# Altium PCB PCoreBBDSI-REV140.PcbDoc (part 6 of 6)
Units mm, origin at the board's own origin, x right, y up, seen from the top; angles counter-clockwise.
Board outline 100 x 72 mm, 6 copper layers (Top Layer, Int1 (GND), Int2 (Sign), Int3 (Sign), Int4 (GND), Bottom Layer), stack 1.551 mm thick; 358 components, 403 nets, 1535 pads, 844 vias.
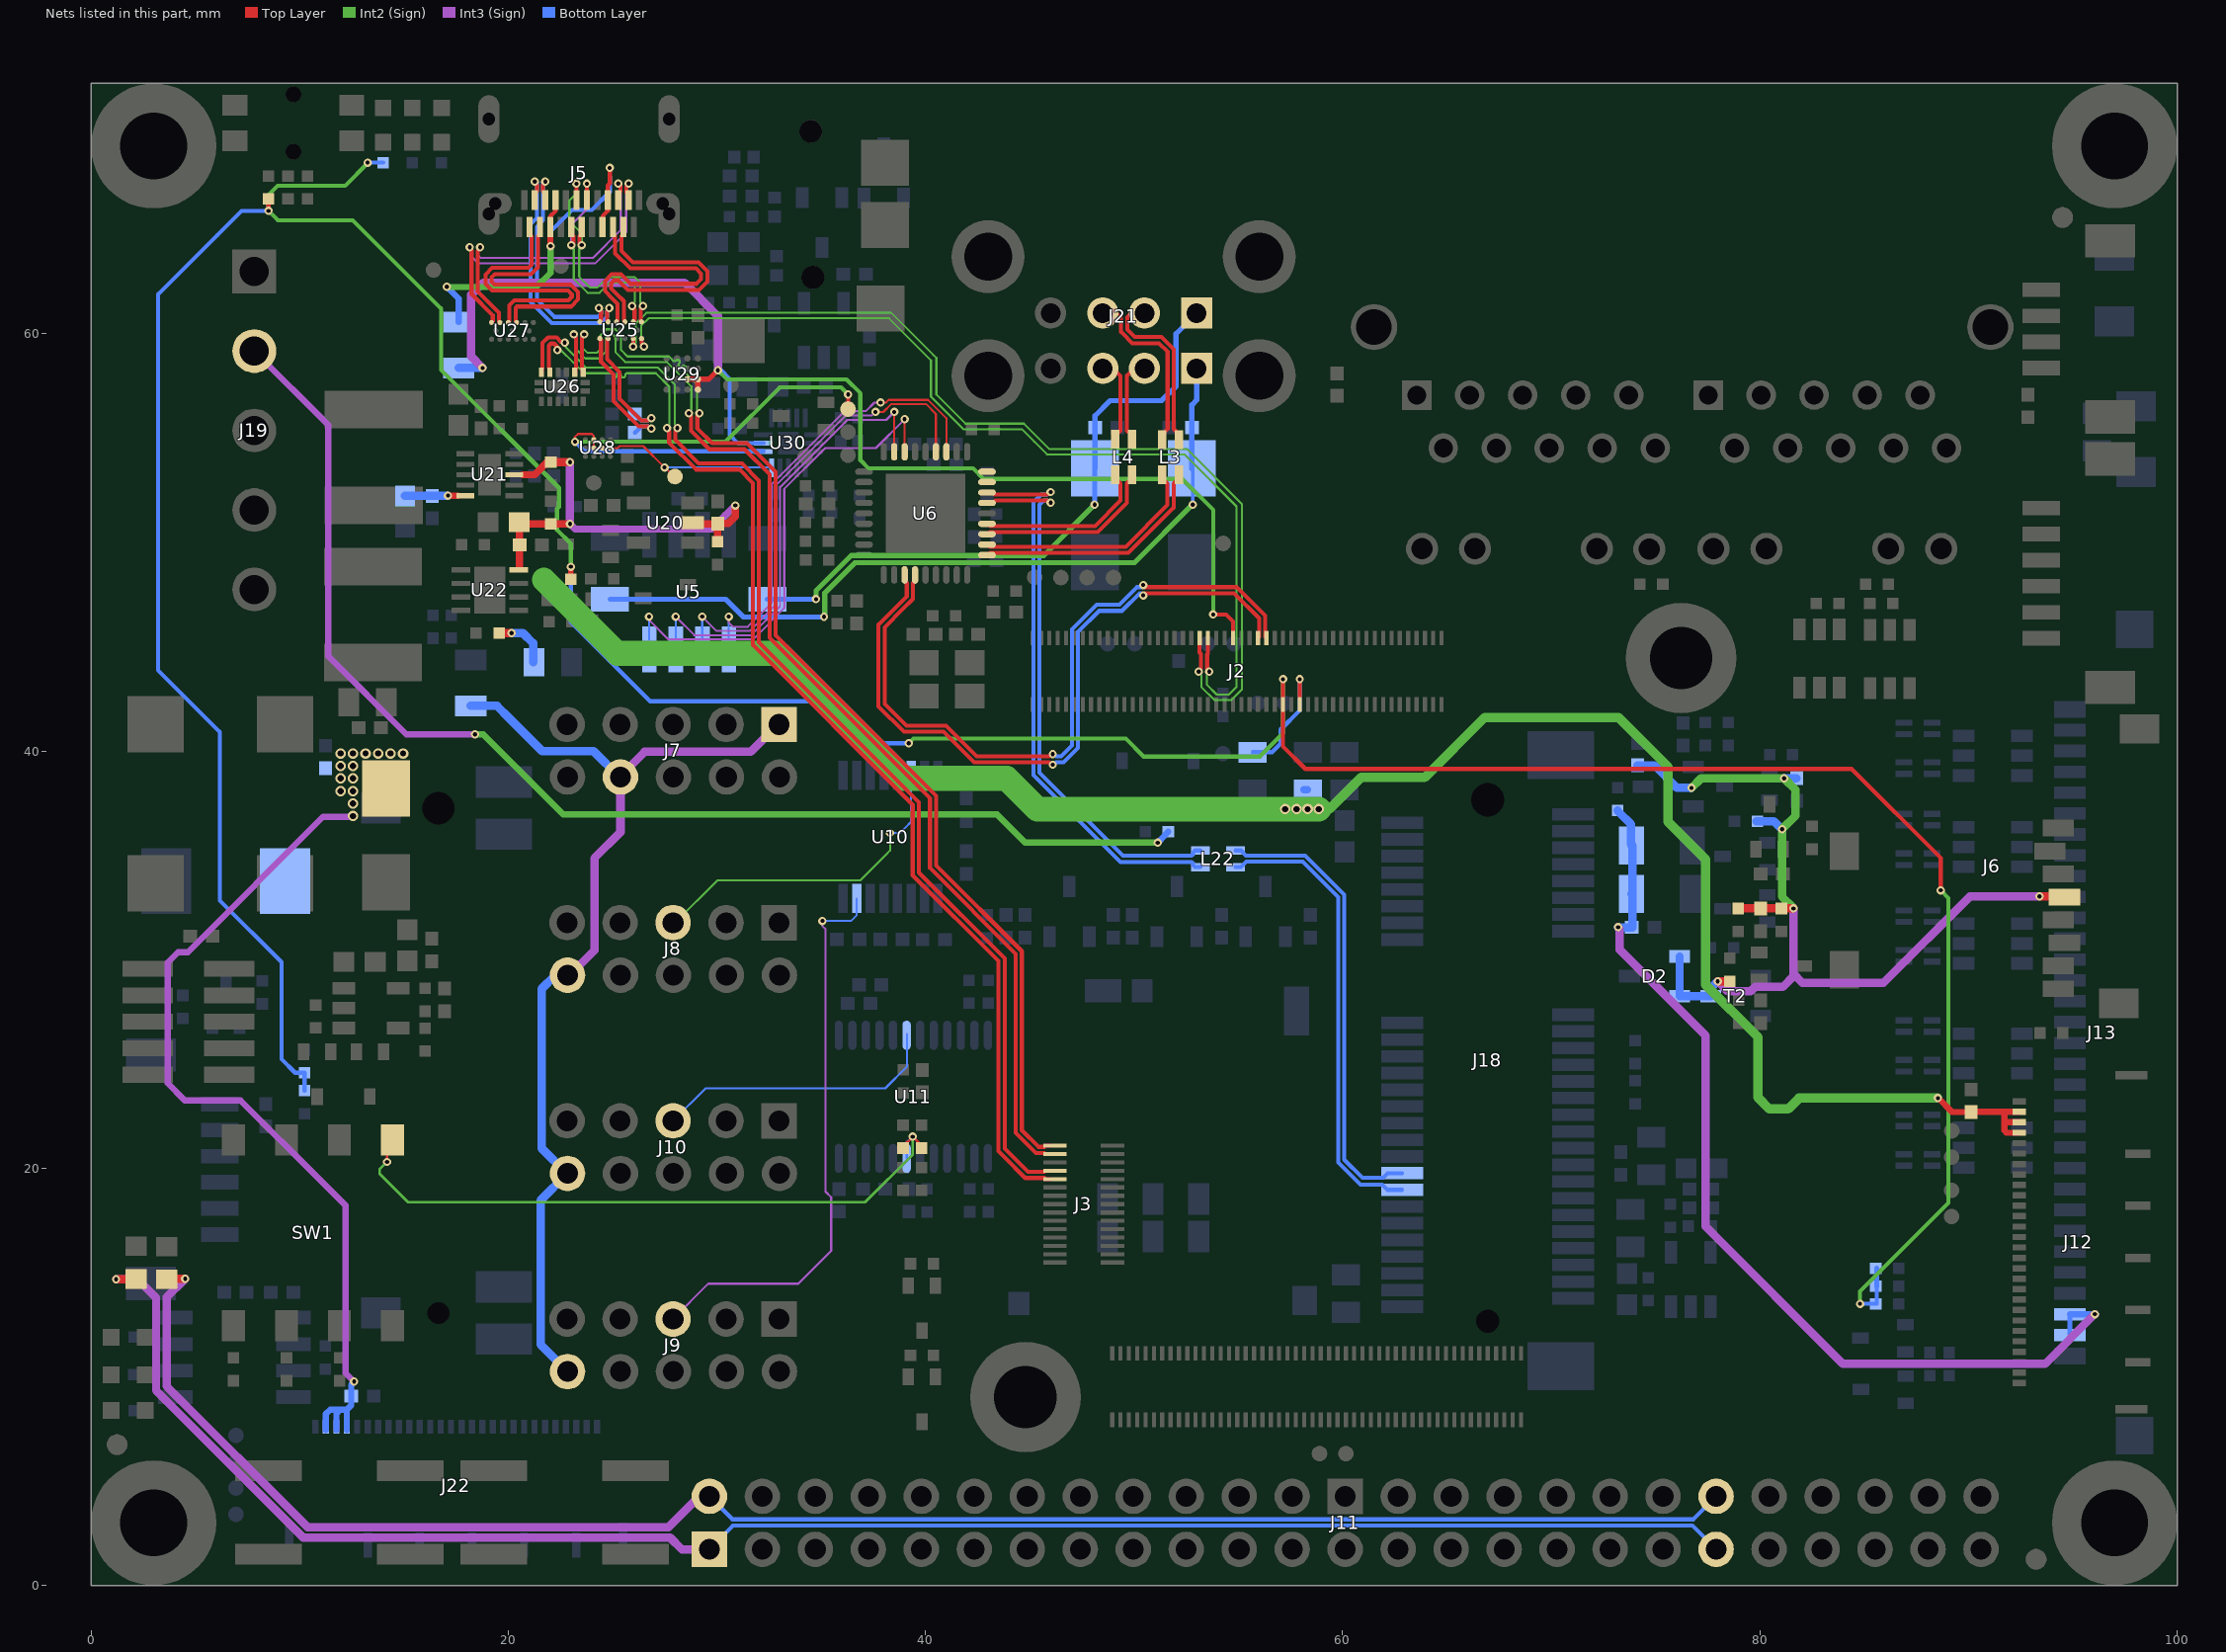
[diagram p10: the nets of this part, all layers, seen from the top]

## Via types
v1: diameter 0.4, hole 0.2, Top Layer to Bottom Layer, tented both sides, 716 vias
v2: diameter 0.5, hole 0.3, Top Layer to Bottom Layer, tented both sides, 102 vias
v3: diameter 0.4, hole 0.2, Top Layer to Bottom Layer, tented bottom, 16 vias
v4: diameter 0.9, hole 0.9, Top Layer to Bottom Layer, 6 vias
v5: diameter 0.5, hole 0.5, Top Layer to Bottom Layer, 2 vias
v6: diameter 3.2, hole 3.2, Top Layer to Bottom Layer, tented both sides, 2 vias

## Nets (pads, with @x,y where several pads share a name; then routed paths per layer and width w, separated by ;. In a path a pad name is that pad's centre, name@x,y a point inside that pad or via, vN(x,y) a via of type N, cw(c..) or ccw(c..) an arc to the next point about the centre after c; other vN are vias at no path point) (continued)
SS_TX2_N: C96.1 U25.C1 | length 6.6
  Top Layer w0.193: U25.C1@24.39,59.77 24.39,59.755 24.443,59.701 24.443,58.652 25.047,58.048 25.047,56.765 26.253,55.558 26.701,55.558 26.804,55.455 v1(26.86,55.455)
  Bottom Layer w0.193: C96.1@26.06,55.265 26.08,55.265 26.293,55.478 26.293,55.496 26.356,55.558 26.701,55.558 26.804,55.455 v1(26.86,55.455)
SS_TX2_P: C95.1 U25.C2 | length 6.1
  Top Layer w0.193: U25.C2@24.79,59.77 24.79,59.755 24.737,59.701 24.737,58.773 25.34,58.17 25.34,56.886 26.375,55.851 26.701,55.851 26.804,55.955 v1(26.86,55.955)
  Bottom Layer w0.193: C95.1@26.06,56.145 26.08,56.145 26.293,55.931 26.293,55.914 26.356,55.851 26.701,55.851 26.804,55.955 v1(26.86,55.955)
SSRX1_N: J5.B10 U27.A2 | length 15.2
  Top Layer w0.193: v1(18.65,64.14) 18.65,64.084 18.533,63.967 18.533,63.622 18.533,62.027 19.549,61.011 19.549,60.606 19.602,60.552 U27.A2@19.602,60.537 ; J5.B10@25.27,66.415 25.27,66.74 J5.B10@25.323,66.793 ; v1(25.27,67.2) 25.27,67.19 25.373,67.087 25.373,66.803 25.363,66.793 J5.B10@25.323,66.793 ; J5.B10@25.37,66.84 J5.B10@25.323,66.793
  Int3 (Sign) w0.1: v1(18.65,64.14) 18.65,64.077 18.531,63.958 18.531,63.79 18.691,63.63 24.05,63.63 25.389,64.969 25.389,67.018 25.27,67.137 v1(25.27,67.2)
SSRX1_P: J5.B11 U27.A1 | length 16.1
  Top Layer w0.193: v1(18.15,64.14) 18.15,64.084 18.24,63.994 18.24,63.743 18.24,61.905 19.256,60.89 19.256,60.606 19.202,60.552 U27.A1@19.202,60.537 ; J5.B11@25.663,66.847 J5.B11@25.667,66.843 ; J5.B11@25.77,66.415 25.77,66.74 J5.B11@25.717,66.793 ; v1(25.77,67.2) 25.77,67.144 25.667,67.041 J5.B11@25.667,66.843 ; J5.B11@25.667,66.843 25.667,66.803 25.677,66.793 J5.B11@25.717,66.793 ; J5.B11@25.667,66.843 J5.B11@25.717,66.793
  Int3 (Sign) w0.1: v1(18.15,64.14) 18.15,64.077 18.269,63.958 18.269,63.682 18.582,63.368 24.158,63.368 25.651,64.861 25.651,67.018 25.77,67.137 v1(25.77,67.2)
SSRX2_N: J5.A10 U27.A4 | length 13.2
  Top Layer w0.193: U27.A4@20.402,60.537 20.402,60.552 20.349,60.606 20.349,61.239 20.411,61.301 23.001,61.301 23.34,61.64 23.34,62.01 22.985,62.365 19.34,62.365 19.203,62.502 19.203,62.712 19.353,62.861 21.086,62.861 21.417,63.192 21.417,64.24 21.417,64.687 21.52,64.79 J5.A10@21.52,65.115
SSRX2_P: J5.A11 U27.A3 | length 13.2
  Top Layer w0.193: U27.A3@20.002,60.537 20.002,60.552 20.056,60.606 20.056,61.361 20.29,61.595 22.88,61.595 23.047,61.762 23.047,61.888 22.863,62.071 19.219,62.071 18.91,62.38 18.91,62.833 19.232,63.155 20.965,63.155 21.123,63.313 21.123,64.24 ; 21.123,64.24 21.123,64.687 21.123,64.24
SSTX1_N: J5.A3 U25.A3 | length 13.4
  Top Layer w0.193: J5.A3@25.02,65.115 25.02,64.79 25.123,64.687 25.123,63.857 25.85,63.13 28.995,63.13 29.247,62.878 29.247,62.612 29.028,62.393 25.862,62.393 25.405,62.85 24.955,62.85 24.637,62.532 24.637,62.048 24.983,61.703 25.243,61.442 25.243,61.04 25.243,60.639 25.19,60.585 U25.A3@25.19,60.57
SSTX1_P: J5.A2 U25.A4 | length 13.4
  Top Layer w0.193: J5.A2@25.52,65.115 25.52,64.79 25.417,64.687 25.417,63.978 25.971,63.423 29.116,63.423 29.54,63 29.54,62.49 29.15,62.1 25.74,62.1 25.283,62.557 25.077,62.557 24.93,62.41 24.93,62.17 25.19,61.91 25.537,61.563 25.537,61.162 25.537,60.639 25.59,60.585 U25.A4@25.59,60.57
SSTX2_N: J5.B3 U25.A1 | length 11.3
  Top Layer w0.193: J5.B3@21.77,66.415 21.77,66.74 21.667,66.843 21.667,67.127 21.773,67.234 v1(21.773,67.29) ; v1(24.34,61.23) 24.34,61.174 24.443,61.071 24.443,60.639 24.39,60.585 U25.A1@24.39,60.57
  Bottom Layer w0.193: v1(21.773,67.29) 21.732,67.29 21.67,67.228 21.67,65.43 21.37,65.13 21.37,61.65 22.212,60.808 24.303,60.808 24.443,60.948 24.443,61.071 24.34,61.174 v1(24.34,61.23)
SSTX2_P: J5.B2 U25.A2 | length 12.3
  Top Layer w0.193: J5.B2@21.27,66.415 21.27,66.74 21.373,66.843 21.373,67.134 21.273,67.234 v1(21.273,67.29) ; U25.A2@24.79,60.57 24.79,60.585 24.737,60.639 24.737,61.071 24.84,61.174 v1(24.84,61.23)
  Bottom Layer w0.193: v1(21.273,67.29) 21.314,67.29 21.377,67.228 21.377,65.552 21.077,65.252 21.077,61.528 22.091,60.514 24.424,60.514 24.737,60.827 24.737,61.071 24.84,61.174 v1(24.84,61.23)
T2IN_DE: R39.2 R42.2 SW1.5 U11.19 | length 32.4
  Top Layer w0.127: v1(14.188,20.3) 14.188,21.088 SW1.5@14.45,21.35 ; R42.2@38.925,20.964 38.925,21.045 v1(39.39,21.51) 39.815,21.085 R39.2@39.815,20.964
  Int2 (Sign) w0.127: v1(14.188,20.3) 13.832,19.944 13.832,19.743 15.205,18.37 37.11,18.37 39.39,20.65 v1(39.39,21.51)
  Bottom Layer w0.127: U11.19@39.095,20.47 39.095,21.215 v1(39.39,21.51)
TXA: J9.5 U10.7 | length 27.5
  Int3 (Sign) w0.1: J9.5@27.9,12.77 29.59,14.46 33.905,14.46 35.48,16.035 35.48,18.61 35.21,18.881 35.21,31.46 35.06,31.61 v1(35.06,31.85)
  Bottom Layer w0.1: v1(35.06,31.85) 36.42,31.85 36.705,32.135 U10.7@36.705,32.93
TXC: J8.5 U10.14 | length 16.1
  Int2 (Sign) w0.1: J8.5@28,31.77 30.03,33.8 36.519,33.8 36.872,33.8 38.1,35.028 38.3,35.228 v1(38.3,36.07)
  Bottom Layer w0.1: v1(38.3,36.07) 38.78,36.07 39.05,36.34 39.305,36.595 U10.14@39.305,38.88
TXD_B_RS232: J10.5 U11.6 | length 13.9
  Bottom Layer w0.1: J10.5@27.9,22.27 29.46,23.83 38.07,23.83 39.105,24.865 U11.6@39.105,26.44
U\S\B\_\H\U\B\_\A\_\O\C\: U5.2 U6.13 | length 22.9
  Top Layer w0.1: v1(37.6,56.25) 37.98,56.25 38.36,56.63 40.02,56.63 40.5,56.15 U6.13@40.5,54.39
  Int3 (Sign) w0.1: v1(29.3,46.44) 29.99,45.75 31.564,45.75 32.83,47.016 32.83,52.727 36.193,56.09 37.44,56.09 v1(37.6,56.25)
  Bottom Layer w0.1: v1(29.3,46.44) 29.3,44.865 U5.2@29.305,44.86
U\S\B\_\H\U\B\_\B\_\O\C\: U5.3 U6.17 | length 22.1
  Top Layer w0.1: U6.17@38.5,54.39 v1(38.5,56.25)
  Int3 (Sign) w0.1: v1(28.03,46.44) 28.92,45.55 31.647,45.55 33.03,46.933 33.03,52.644 36.256,55.87 38.12,55.87 v1@38.5,56.25
  Bottom Layer w0.1: v1(28.03,46.44) 28.03,44.865 U5.3@28.035,44.86
USB1_CC1: TP9.1 U28.A2 U30.13 | length 8.9
  Top Layer w0.1: U28.A2@24.9,54.52 25.25,54.52 25.25,54.522 25.338,54.61 26.47,54.61 v1(27.49,53.59) 27.52,53.59 27.96,53.15 TP9.1@27.99,53.15
  Bottom Layer w0.1: v1(27.49,53.59) 32.6,53.59 U30.13@32.63,53.56
USB1_CC2: TP10.1 U28.B2 U28.C1 U28.C2 U30.14 | length 26.5
  Top Layer w0.1: v1(23.2,54.82) 23.2,54.99 23.17,55.02 23.345,55.195 24.005,55.195 24.1,55.1 U28.C1@24.1,54.92 U28.C2@24.1,54.52 ; U28.C2@24.1,54.52 U28.B2@24.5,54.52
  Top Layer w0.2: TP10.1@36.29,56.39 v1(36.29,57.09)
  Int2 (Sign) w0.2: v1(23.2,54.82) 30.41,54.82 33.02,57.43 34.054,57.43 34.386,57.43 35.95,57.43 v1(36.29,57.09)
  Bottom Layer w0.2: v1(23.2,54.82) 23.66,54.36 U30.14@32.23,54.36
USB1_CN_D_N: J5.A7 J5.B7 U25.A5 | length 12
  Top Layer w0.193: v1(23.02,64.25) 23.033,64.25 23.123,64.34 23.123,64.586 23.123,64.687 23.02,64.79 J5.A7@23.02,65.115 ; J5.B7@23.77,66.415 v1(23.77,67.19) ; v1(25.94,61.33) 25.94,61.274 26.054,61.16 26.054,60.649 25.99,60.585 U25.A5@25.99,60.57
  Int2 (Sign) w0.1: v1(23.02,64.25) 23.02,64.187 23.139,64.068 23.139,63.9 23.139,62.623 23.802,61.96 24.38,61.96 24.878,62.458 25.952,62.458 26.07,62.34 26.07,61.828 26.07,61.512 25.94,61.383 v1(25.94,61.33)
  Int3 (Sign) w0.1: v1(23.02,64.25) 23.02,65.22 23.77,65.97 v1(23.77,67.19)
USB1_CN_D_P: J5.A6 J5.B6 U25.A6 | length 12.1
  Top Layer w0.193: J5.B6@23.27,66.415 v1(23.27,67.19) ; v1(23.52,64.25) 23.507,64.25 23.417,64.34 23.417,64.465 23.417,64.687 23.52,64.79 J5.A6@23.52,65.115 ; U25.A6@26.39,60.57 26.39,60.585 26.347,60.628 26.347,61.211 v1(26.461,61.325)
  Int2 (Sign) w0.1: v1(23.27,67.19) 23.27,66.7 23.25,66.7 22.93,66.38 22.93,65.401 23.52,64.811 v1(23.52,64.25) 23.52,64.187 23.401,64.068 23.401,63.792 23.401,62.731 23.91,62.222 24.272,62.222 24.77,62.72 26.06,62.72 26.331,62.449 26.331,61.507 26.461,61.377 v1(26.461,61.325)
USB1_OTG_VBUS: F2.1 J5.A4 J5.A9 J5.B4 J5.B9 | length 19.2
  Top Layer w0.2: J5.A9@22.02,65.115 22.02,65.638 22.27,65.888 J5.B4@22.27,66.415 ; J5.A4@24.52,65.115 24.52,65.64 24.77,65.89 J5.B9@24.77,66.415 24.77,67.104 24.87,67.204 24.87,67.94 v1(24.86,67.95)
  Top Layer w0.3: J5.A9@22.02,65.115 22.02,64.21 v1(22.03,64.2)
  Int2 (Sign) w0.3: v1(17.06,62.25) 17.068,62.242 21.352,62.242 22.03,62.92 v1(22.03,64.2)
  Bottom Layer w0.2: v1(22.03,64.2) 22.064,64.234 22.064,64.934 23.06,65.93 24,65.93 24.87,66.8 24.87,67.536 24.86,67.546 v1(24.86,67.95)
  Bottom Layer w0.3: v1(17.06,62.25) 17.63,61.68 F2.1@17.63,60.56
USB1_OTG_VBUS_F: F2.2 J2.51 U29.C2 U29.D1 U29.D2 U30.15 | length 62.8
  Top Layer w0.2: v1(53.79,46.54) 54.41,46.54 54.74,46.21 J2.51@54.74,45.41
  Top Layer w0.25: U29.C2@28.59,57.82 U29.D2@29.09,57.82 ; U29.D1@29.09,57.32 U29.D2@29.09,57.82 ; v1(30.05,58.25) 29.62,57.82 U29.D2@29.09,57.82
  Int2 (Sign) w0.2: v1(30.05,58.25) 30.49,57.81 36.21,57.81 36.88,57.14 36.88,53.94 37.27,53.55 42.28,53.55 42.79,53.04 52.3,53.04 53.79,51.55 v1(53.79,46.54)
  Int3 (Sign) w0.4: v1(18.77,58.36) 18.22,58.91 18.22,61.87 18.8,62.45 28.45,62.45 30.05,60.85 v1(30.05,58.25)
  Bottom Layer w0.2: v1(30.05,58.25) 30.2,58.25 30.61,57.84 30.61,55.15 31,54.76 U30.15@32.23,54.76
  Bottom Layer w0.4: F2.2@17.63,58.36 v1(18.77,58.36)
USB1_RX_N: J3.23 U26.14 | length 55.8
  Top Layer w0.193: U26.14@21.59,58.16 21.618,58.188 21.618,58.326 21.643,58.351 21.643,59.553 21.91,59.82 22.316,59.82 v1@22.52,59.615 ; v1@28.107,55.424 28.004,55.321 28.004,54.911 29.131,53.783 31.197,53.783 32.016,52.964 32.016,45.204 39.68,37.541 39.68,34.165 43.793,30.052 43.793,20.937 44.907,19.823 45.691,19.823 45.744,19.876 J3.23@45.994,19.876
  Int2 (Sign) w0.1: v1@22.748,59.613 22.748,59.36 23.201,58.907 23.739,58.37 24,58.37 25.42,58.37 27.179,58.37 27.985,57.564 27.985,55.662 28.107,55.54 v1(28.107,55.48)
  other v1: 22.706,59.576
USB1_RX_P: J3.21 U26.13 | length 55.9
  Top Layer w0.193: U26.13@21.99,58.16 21.962,58.188 21.962,58.326 21.937,58.351 21.937,59.432 22.032,59.527 22.194,59.527 v1@22.313,59.408 ; v1(27.607,55.48) 27.607,55.424 27.71,55.321 27.71,54.789 29.01,53.49 31.076,53.49 31.723,52.843 31.723,45.083 39.386,37.419 39.386,34.044 43.5,29.93 43.5,20.815 43.927,20.388 44.643,19.673 44.786,19.529 45.691,19.529 45.744,19.476 J3.21@45.994,19.476
  Int2 (Sign) w0.1: v1(22.352,59.222) 22.395,59.18 22.558,59.18 23.093,58.646 23.63,58.108 24.66,58.108 24.91,58.108 cw(c24.91,58.008) 25.01,58.008 25.01,58 ccw(c25.11,58) 25.21,58 25.21,58.008 cw(c25.31,58.008) 25.41,58.008 25.41,58 ccw(c25.51,58) 25.61,58 25.61,58.008 cw(c25.71,58.008) 25.71,58.108 25.953,58.108 27.07,58.108 27.723,57.455 27.723,55.656 27.607,55.54 v1(27.607,55.48)
USB1_TX_N: J3.29 U26.9 | length 56
  Top Layer w0.193: U26.9@23.59,58.16 23.562,58.188 23.562,58.326 23.537,58.351 23.537,59.811 23.64,59.914 v1(23.64,59.97) ; v1(29.163,56.19) 29.163,56.134 29.06,56.031 29.06,55.465 29.772,54.753 31.447,54.753 32.823,53.377 32.823,45.54 40.51,37.853 40.51,34.51 44.62,30.4 44.62,21.813 45.41,21.023 45.691,21.023 45.744,21.076 J3.29@45.994,21.076
  Int2 (Sign) w0.1: v1(23.64,59.97) 23.64,59.91 23.517,59.788 23.517,59.363 23.8,59.08 24.241,59.08 24.418,59.257 24.418,59.924 24.706,60.212 25.129,60.212 25.41,59.931 25.41,59.214 25.714,58.91 27.709,58.91 27.907,58.712 ccw(c27.978,58.783) 28.048,58.712 28.054,58.718 cw(c28.125,58.647) 28.196,58.718 cw(c28.125,58.647) 28.196,58.576 28.19,58.57 ccw(c28.26,58.5) 28.19,58.429 ccw(c28.26,58.5) 28.331,58.429 28.337,58.435 cw(c28.408,58.364) 28.478,58.435 cw(c28.408,58.364) 28.478,58.293 28.473,58.288 ccw(c28.543,58.217) 28.473,58.146 28.649,57.969 29.041,57.578 29.041,56.372 29.163,56.25 v1(29.163,56.19)
USB1_TX_P: J3.27 U26.10 | length 56
  Top Layer w0.193: v1(23.14,59.97) 23.14,59.914 23.243,59.811 23.243,58.351 23.218,58.326 23.218,58.188 U26.10@23.19,58.16 ; v1(28.663,56.19) 28.663,56.134 28.766,56.031 28.766,55.344 29.65,54.46 31.325,54.46 32.53,53.255 32.53,45.418 40.217,37.732 40.217,34.388 44.327,30.278 44.327,21.691 45.288,20.729 45.691,20.729 45.744,20.676 J3.27@45.994,20.676
  Int2 (Sign) w0.1: v1(23.14,59.97) 23.14,59.91 23.256,59.795 23.256,59.254 23.692,58.818 24.349,58.818 24.68,59.149 24.68,59.816 24.814,59.95 25.021,59.95 25.148,59.823 25.148,59.105 25.605,58.648 27.6,58.648 28.779,57.47 28.779,56.365 28.663,56.25 v1(28.663,56.19)
USB_HUB_A_EN: U5.1 U6.12 | length 22.2
  Top Layer w0.1: v1(37.85,56.7) 38.1,56.7 38.23,56.83 40.12,56.83 41,55.95 U6.12@41,54.39
  Int3 (Sign) w0.1: v1(30.57,46.44) 30.57,46.14 30.76,45.95 31.481,45.95 32.63,47.099 32.63,52.81 36.11,56.29 37.14,56.29 37.55,56.7 v1(37.85,56.7)
  Bottom Layer w0.1: v1(30.57,46.44) 30.57,44.865 U5.1@30.575,44.86
USB_HUB_A_N: J21.A2 L3.3 | length 8.5
  Top Layer w0.193: J21.A2@50.5,60.99 49.87,60.99 49.67,60.79 49.67,60.21 50.04,59.84 51.317,59.84 51.9,59.257 51.9,55.43 52.15,55.18 L3.3@52.15,54.93
USB_HUB_A_P: J21.A3 L3.2 | length 8.6
  Top Layer w0.193: J21.A3@48.5,60.99 49.16,60.99 49.377,60.773 49.377,60.088 49.43,60.035 49.918,59.547 51.196,59.547 51.607,59.136 51.607,55.437 51.35,55.18 L3.2@51.35,54.93
USB_HUB_A_PWR: C4.1 C6.2 J21.A1 L1.1 | length 30.5
  Int2 (Sign) w0.25: v1(34.752,47.275) 34.752,47.689 36.434,49.37 45.67,49.37 v1(48.11,51.81)
  Bottom Layer w0.25: L1.1@32.43,47.275 v1(34.752,47.275)
  Bottom Layer w0.254: v1(48.11,51.81) 48.11,53.53 C4.1@48.12,53.54 48.13,53.55 C6.2@48.13,55.5 48.13,56.07 48.85,56.79 51.32,56.79 52.01,57.48 52.01,60 J21.A1@53,60.99
USB_HUB_B_EN: U5.4 U6.16 | length 23.6
  Top Layer w0.1: U6.16@39,54.39 v1(39,55.9)
  Int3 (Sign) w0.1: v1(26.75,46.44) 26.807,46.383 26.807,46.22 27.677,45.35 31.73,45.35 33.23,46.85 33.23,52.561 35.189,54.52 37.294,54.52 37.62,54.52 v1(39,55.9)
  Bottom Layer w0.1: v1(26.75,46.44) 26.75,44.875 U5.4@26.765,44.86
USB_HUB_B_N: J21.B2 L4.3 | length 4.2
  Top Layer w0.193: L4.3@49.9,54.94 49.9,55.19 49.797,55.293 49.709,55.293 49.647,55.356 49.647,56.842 49.647,57.987 50,58.34 J21.B2@50.5,58.34
USB_HUB_B_P: J21.B3 L4.2 | length 4.2
  Top Layer w0.193: J21.B3@48.5,58.34 48.98,58.34 49.353,57.967 49.353,56.963 49.353,55.356 49.291,55.293 49.203,55.293 49.1,55.19 L4.2@49.1,54.94
USB_HUB_B_PWR: C5.1 C7.2 J21.B1 L2.1 | length 37.8
  Int2 (Sign) w0.25: v1(35.135,46.435) 35.177,46.477 35.177,47.099 35.177,47.576 36.621,49.02 50.02,49.02 v1(52.81,51.81)
  Bottom Layer w0.166: C5.1@52.764,53.54 52.81,53.494 v1(52.81,51.81)
  Bottom Layer w0.25: L2.1@24.88,47.275 30.415,47.275 31.27,46.42 35.12,46.42 v1(35.135,46.435)
  Bottom Layer w0.254: C5.1@52.764,53.54 52.77,53.546 52.77,56.585 53,56.815 J21.B1@53,58.34
USB_OTG_D_N: J2.59 U25.C5 | length 49.2
  Top Layer w0.193: v1(25.987,59.39) 25.988,59.392 U25.C5@25.99,59.77 U25.C5@25.99,59.77 ; v1(53.103,43.8) 53.103,43.856 53.206,43.959 53.206,44.654 53.14,44.72 J2.59@53.14,45.19
  Int2 (Sign) w0.1: v1(25.987,59.39) 25.987,59.443 26.106,59.562 26.106,59.91 26.106,60.487 26.619,61 38.325,61 38.36,61 40.383,58.977 40.522,58.838 40.522,57.087 41.921,55.688 42.919,55.688 42.922,55.692 43.678,55.692 43.681,55.688 44.167,55.688 44.722,55.688 45.93,54.48 52.525,54.48 55.172,51.834 55.172,42.956 54.654,42.438 53.856,42.438 53.222,43.073 53.222,43.618 53.103,43.737 v1(53.103,43.8)
USB_OTG_D_P: J2.57 U25.C6 | length 47.5
  Top Layer w0.193: U25.C6@26.39,59.77 26.401,59.759 26.401,59.543 26.508,59.436 v1(26.508,59.381) ; J2.57@53.54,45.19 53.537,45.187 53.537,44.657 53.499,44.62 53.499,43.959 53.603,43.856 v1(53.603,43.8)
  Int2 (Sign) w0.1: v1(26.508,59.381) 26.508,59.433 26.368,59.573 26.368,60.018 26.368,60.379 26.727,60.738 38.252,60.738 40.26,58.73 40.26,57.354 40.26,56.979 41.812,55.427 42.187,55.427 43.027,55.427 43.031,55.43 43.569,55.43 43.573,55.427 44.613,55.427 45.21,54.83 45.822,54.218 52.417,54.218 54.91,51.725 54.91,43.065 54.545,42.7 53.965,42.7 53.483,43.181 53.483,43.618 53.603,43.737 v1(53.603,43.8)
USBD_N: J2.45 U6.30 | length 34.5
  Top Layer w0.193: U6.30@39,48.39 39,48.153 39.103,48.049 39.103,47.405 38.807,47.108 37.75,46.052 37.75,42.14 38.97,40.92 40.865,40.92 42.337,39.448 45.936,39.448 46.044,39.34 v1(46.1,39.34) ; v1(50.44,47.457) 50.44,47.48 50.52,47.56 54.793,47.56 55.993,46.36 55.993,45.463 J2.45@55.94,45.41
  Bottom Layer w0.193: v1(46.1,39.34) 46.156,39.34 46.264,39.448 46.618,39.448 47.31,40.14 47.31,45.7 48.326,46.716 49.416,46.716 50.26,47.56 50.337,47.56 v1(50.44,47.457)
USBD_P: J2.43 U6.31 | length 34.5
  Top Layer w0.193: U6.31@39.5,48.39 39.5,48.153 39.397,48.049 39.397,47.283 38.928,46.815 38.043,45.93 38.043,42.262 39.092,41.213 40.987,41.213 42.458,39.742 45.936,39.742 46.044,39.85 v1(46.1,39.85) ; v1(50.44,47.957) 50.44,47.933 50.52,47.853 54.915,47.853 56.287,46.482 56.287,45.463 J2.43@56.34,45.41
  Bottom Layer w0.193: v1(46.1,39.85) 46.156,39.85 46.264,39.742 46.497,39.742 47.016,40.262 47.016,45.672 47.016,45.821 48.205,47.01 48.354,47.01 49.295,47.01 50.138,47.853 50.337,47.853 v1(50.44,47.957)
USBDM1_N: L3.4 U6.1 | length 11.6
  Top Layer w0.193: U6.1@43,49.39 43.103,49.493 49.723,49.493 51.897,51.667 51.897,52.814 51.959,52.877 52.047,52.877 52.15,52.98 L3.4@52.15,53.23
USBDM1_P: L3.1 U6.2 | length 11.1
  Top Layer w0.193: U6.2@43,49.89 43.103,49.787 49.602,49.787 51.603,51.788 51.603,52.814 51.541,52.877 51.453,52.877 51.35,52.98 L3.1@51.35,53.23
USBDM2_N: L4.4 U6.3 | length 8.8
  Top Layer w0.193: U6.3@43,50.39 43.1,50.49 48.25,50.49 49.647,51.887 49.647,52.824 49.709,52.887 49.797,52.887 49.9,52.99 L4.4@49.9,53.24
USBDM2_P: L4.1 U6.4 | length 8.3
  Top Layer w0.193: U6.4@43,50.89 43.106,50.783 48.128,50.783 49.353,52.008 49.353,52.824 49.291,52.887 49.203,52.887 49.1,52.99 L4.1@49.1,53.24
USBDM3_N: L22.2 U6.6 | length 26.1
  Top Layer w0.193: U6.6@42.95,51.89 43.237,51.89 43.347,52 45.844,52 45.944,51.9 v1(46,51.9)
  Bottom Layer w0.193: v1(46,51.9) 45.944,51.9 45.836,52.008 45.673,52.008 45.47,51.805 45.47,38.968 49.462,34.977 52.754,34.977 52.817,35.039 52.817,35.127 52.92,35.23 L22.2@53.17,35.23
USBDM3_P: L22.3 U6.7 | length 27.1
  Top Layer w0.193: U6.7@42.95,52.39 43.237,52.39 43.334,52.293 45.827,52.293 45.944,52.41 v1(46,52.41)
  Bottom Layer w0.193: v1(46,52.41) 45.944,52.41 45.836,52.302 45.552,52.302 45.177,51.927 45.177,38.847 49.34,34.683 52.754,34.683 52.817,34.621 52.817,34.533 52.92,34.43 L22.3@53.17,34.43
USBDM4_N: U6.8
USBDM4_P: U6.9
USBHUB_C_N: J18.36 L22.1 | length 22
  Bottom Layer w0.193: L22.1@54.87,35.23 55.12,35.23 55.367,34.983 58.207,34.983 60.08,33.11 60.08,20.407 60.944,19.543 61.933,19.543 62.15,19.76 J18.36@62.85,19.76
USBHUB_C_P: J18.38 L22.4 | length 22
  Bottom Layer w0.193: L22.4@54.87,34.43 55.12,34.43 55.38,34.69 58.085,34.69 59.787,32.988 59.787,20.285 59.79,20.282 60.859,19.213 61.897,19.213 62.15,18.96 J18.38@62.85,18.96
V5OUT: J11.2 J11.40 L9.1 | length 85
  Top Layer w0.4: L9.1@3.62,14.675 3.645,14.7 v1(4.51,14.7)
  Int3 (Sign) w0.4: v1(4.51,14.7) 3.62,13.81 3.62,9.55 10.38,2.79 27.681,2.79 28.912,4.021 29.391,4.021 J11.2@29.64,4.27
  Bottom Layer w0.2: J11.2@29.64,4.27 30.74,3.17 76.82,3.17 77.9,4.25 J11.40@77.9,4.27
V33OUT: J11.1 J11.39 L8.2 | length 86.6
  Top Layer w0.4: v1(1.2,14.68) 1.205,14.685 L8.2@2.165,14.685
  Int3 (Sign) w0.4: v1(1.2,14.68) 2.22,14.68 3.12,13.78 3.12,10.653 3.12,9.343 10.173,2.29 27.76,2.29 28.32,1.73 J11.1@29.64,1.73
  Bottom Layer w0.2: J11.1@29.64,1.73 29.64,1.74 30.77,2.87 76.76,2.87 J11.39@77.9,1.73
VBAT_IN: J19.2 R78.2 | length 60.3
  Int2 (Sign) w0.3: 45.8,35.61 51.12,35.61 v1(51.13,35.6)
  Int2 (Sign) w0.305: v1(18.41,40.8) 18.8,40.8 22.65,36.95 43.433,36.95 44.773,35.61 45.8,35.61
  Int3 (Sign) w0.305: J19.2@7.825,59.17 11.38,55.615 11.38,44.539 15.119,40.8 v1(18.41,40.8)
  Bottom Layer w0.3: v1(51.13,35.6) 51.515,35.985 51.515,36.005 R78.2@51.64,36.13
VCC_COM: F1.2 J7.1 J7.8 J8.10 J9.10 J10.10 | length 49.2
  Int3 (Sign) w0.406: J8.10@22.94,29.25 24.13,30.44 24.13,34.86 25.38,36.11 J7.8@25.38,38.75 ; J7.8@25.33,38.75 26.54,39.96 31.62,39.96 J7.1@32.93,41.27
  Bottom Layer w0.406: F1.2@18.2,42.16 19.46,42.16 20.04,41.58 21.63,39.99 24.09,39.99 J7.8@25.33,38.75 ; J9.10@22.84,10.25 21.55,11.54 21.55,18.46 22.82,19.73 21.6,20.95 21.6,28.6 22.23,29.23 J8.10@22.92,29.23
VDD_3V3: J2.40 R3.2 R4.2 R5.1 R8.1 R9.1 R68.2 R73.1 R82.2 | length 187
  Top Layer w0.2: v1(8.51,65.89) R68.2@8.51,66.46 ; J2.40@57.138,42.519 v1(57.138,43.44) ; J2.40@57.14,42.45 57.14,40.21 58.21,39.14 84.39,39.14 88.67,34.86 v1(88.67,33.32)
  Top Layer w0.254: R73.1@23,48.24 v1(23,48.83)
  Int2 (Sign) w0.2: v1(13.26,68.2) 13.26,68.17 12.18,67.09 8.94,67.09 8.51,66.66 v1(8.51,65.89) 8.96,65.44 12.544,65.44 16.78,61.204 16.78,58.26 22.43,52.61 22.43,51.707 22.34,51.617 22.34,50.594 23,49.934 v1(23,48.83) ; v1(39.2,40.37) 39.42,40.59 49.6,40.59 50.46,39.73 56.03,39.73 57.14,40.84 57.14,43.438 v1(57.138,43.44) ; v1(84.8,13.5) 84.8,14.1 89.04,18.34 89.04,32.95 v1(88.67,33.32)
  Bottom Layer w0.2: v1(8.51,65.89) 7.22,65.89 6.04,64.71 3.22,61.89 3.22,43.87 6.18,40.91 6.18,32.83 9.13,29.88 9.13,25.23 9.785,24.575 R3.2@10.23,24.575 R4.2@10.23,23.715 ; v1@13.26,68.2 R82.2@14,68.2 ; v1(23,48.83) 23,46.184 26.799,42.385 34.475,42.385 36.49,40.37 v1(39.2,40.37) ; v1(84.8,13.5) R8.1@85.55,13.5 85.6,13.5 R5.1@85.6,14.35
  Bottom Layer w0.254: R5.1@85.6,14.35 R9.1@85.6,15.2
VDD_SDCARD: C19.2 C22.2 C23.2 D2.1 D2.2 J6.4 R19.2 R20.2 R21.2 R27.2 T2.3 | length 46.4
  Top Layer w0.1: J6.4@94.57,33.03 J6.4@94.6,33
  Top Layer w0.4: v1(77.98,28.96) R21.2@78.56,28.96 ; R19.2@78.96,32.45 R20.2@81.03,32.45 v1(81.61,32.45) ; v1(93.4,33.03) J6.4@94.57,33.03
  Int2 (Sign) w0.4: v1@76.724,38.23 v1(76.72,38.23) 77.18,38.69 v1(81.16,38.69) 81.71,38.14 81.71,36.9 v1(81.06,36.25) 81.06,33.02 81.61,32.47 v1(81.61,32.45)
  Int3 (Sign) w0.4: v1(77.98,28.96) 78.46,28.48 79.55,28.48 79.76,28.69 81.097,28.69 81.61,29.203 81.61,29.309 ; v1(81.61,32.45) 81.61,29.309 ; v1(93.4,33.03) 90.07,33.03 85.93,28.89 82.028,28.89 81.61,29.309
  Bottom Layer w0.4: C23.2@74.13,39.31 74.94,39.31 76.02,38.23 v1(76.72,38.23) ; D2.1@76.15,30.15 D2.2@76.15,28.25 T2.3@77.64,28.25 77.643,28.253 77.643,28.623 v1(77.98,28.96) ; R27.2@79.83,36.63 R27.2@79.88,36.63 80.67,36.63 81.05,36.25 v1(81.06,36.25) ; v1(81.16,38.69) C22.2@81.76,38.69
VDD_VBAT: J2.36 R76.2 | length 5.9
  Top Layer w0.2: J2.36@57.938,42.519 57.938,42.791 ; 57.94,42.791 v1(57.94,43.44)
  Bottom Layer w0.2: R76.2@55.69,39.94 56.62,39.94 57.03,40.35 57.03,41.03 57.94,41.94 v1(57.94,43.44)
VIN: C46.2 C69.2 C71.2 C72.1 C77.2 C78.2 C79.2 C80.2 C106.2 D9.1 J12.25 J12.26 J12.27 J22.25 J22.26 J22.27 R2.2 R62.2 R63.1 R65.1 R66.1 R71.1 U20.2 U21.5 U21.8 U22.4 | length 165.2
  Top Layer w0.2: U21.8@20.28,53.24 U21.8@20.703,53.24
  Top Layer w0.3: v1(17.11,52.24) 17.25,52.24 U21.5@17.615,52.24 ; v1(88.53,23.36) 88.54,23.36 89.21,22.69 C46.2@90.12,22.69 90.13,22.7 91.718,22.7 ; J12.25@92.435,21.7 91.814,21.7 91.718,21.797 91.718,22.332 ; J12.26@92.435,22.2 91.85,22.2 91.718,22.332 ; J12.27@92.435,22.7 91.718,22.7 ; 91.718,22.332 91.718,22.7
  Top Layer w0.35: C79.2@20.53,50.96 C79.2@20.54,50.95 ; U22.4@20.54,48.76 C80.2@20.54,49.88 C79.2@20.54,50.95 ; U21.8@20.703,53.24 21.265,53.24 R66.1@21.865,53.84 ; v1(22.96,50.88) R65.1@22.04,50.88 20.61,50.88 C79.2@20.54,50.95 ; U20.2@28.84,50.94 28.89,50.89 C69.2@30.04,50.89 ; R62.2@30.04,50.03 C69.2@30.04,50.89 ; v1(30.89,51.77) 30.89,51.24 30.56,50.91 30.06,50.91 C69.2@30.04,50.89
  Top Layer w0.406: R71.1@19.51,45.65 R71.1@19.56,45.65 v1(20.16,45.65) ; R66.1@22.04,53.84 v1(22.96,53.84)
  Int2 (Sign) w0.45: v2@58.885,37.379 58.885,37.249 58.86,37.224 v2(58.86,37.21) 59.366,37.21 60.881,38.725 63.925,38.725 66.81,41.61 73.22,41.61 75.6,39.23 75.6,36.594 77.355,34.839 77.39,34.804 77.39,28.8 79.91,26.28 79.91,23.38 80.45,22.84 81.36,22.84 81.88,23.36 v1(88.53,23.36)
  Int2 (Sign) w1.15: 21.71,48.21 25.24,44.68
  Int2 (Sign) w1.2: 25.24,44.68 32.96,44.68 38.96,38.68 43.899,38.68 45.369,37.21 v2(57.24,37.21) v2(57.78,37.21) v2(58.32,37.21) v2(58.86,37.21)
  Int3 (Sign) w0.3: v2@12.56,36.84 11.12,36.84 4.64,30.36 4.17,30.36 3.67,29.86 3.67,24.07 4.49,23.25 7.165,23.25 10.96,19.455 12.2,18.215 12.2,10.18 v1(12.61,9.77)
  Int3 (Sign) w0.35: v1@22.97,50.87 23.205,50.635 29.755,50.635 v1(30.89,51.77)
  Int3 (Sign) w0.406: v1(22.96,50.88) v1(22.96,53.84)
  Bottom Layer w0.3: J22.27@11.26,7.46 J22.27@11.26,7.61 11.26,8.22 11.46,8.42 11.94,8.42 ; J22.26@11.76,7.46 J22.26@11.76,7.61 11.76,8.24 11.94,8.42 ; J22.25@12.26,7.46 J22.25@12.26,7.61 12.26,8.42 ; v1(12.61,9.77) 12.61,9.763 12.47,9.623 C106.2@12.47,9.07 12.47,8.63 12.26,8.42 ; 11.94,8.42 12.26,8.42
  Bottom Layer w0.35: R2.2@58.145,38.14 R2.2@58.32,38.14
  Bottom Layer w0.4: C77.2@15.05,52.24 C78.2@16.35,52.24 ; C78.2@16.36,52.24 v1(17.11,52.24)
  Bottom Layer w0.406: v1(20.16,45.65) 20.705,45.65 21.19,45.165 R63.1@21.19,44.26
  other v2: 12.56,36.88 12.56,37.48 11.96,38.08 12.56,38.08 11.96,38.68 12.56,38.68 11.96,39.28 12.56,39.28 11.96,39.88 12.56,39.88 13.16,39.88 13.76,39.88 14.36,39.88 14.96,39.88
VLCD: C45.2 J13.29 J13.30 L11.2 L16.2 R49.2 | length 47.3
  Int3 (Sign) w0.4: v1(73.2,31.55) 73.281,31.469 73.281,30.469 77.4,26.35 77.4,17.2 83.98,10.62 93.67,10.62 v1(96.05,13)
  Bottom Layer w0.254: J13.30@94.86,12 J13.29@94.86,13
  Bottom Layer w0.3: J13.29@94.86,13 v1(96.05,13)
  Bottom Layer w0.4: R49.2@73.17,37.14 73.245,37.065 73.819,36.491 73.819,35.551 L11.2@73.862,35.508 ; v1(73.2,31.55) 73.21,31.54 C45.2@73.86,31.54 73.9,31.54 L16.2@73.9,33.15 ; L16.2@73.845,33.15 L16.2@73.9,33.15 ; L11.2@73.845,35.47 73.9,35.47 L16.2@73.9,33.15
pads on no net: A-REF1.1 A-REF2.1 A-REF3.1 A-REF4.1 A-REF5.1 A-REF6.1 D1.2 D3.1 D6.1 D10.2 D12.2 J3.1 J3.3 J3.7 J3.9 J4.None J7.6 J7.7 J7.9 J7.10 J8.1 J8.2 J8.4 J8.6 J8.7 J8.8 J9.1 J9.2 J9.4 J9.6 J9.7 J9.8 J10.1 J10.2 J10.7 J10.8 J11.43 J12.40 J12.41 J13.31 J13.32 J13.33 J13.34 J14.9 J14.10 J15.9 J15.10 J16.L11 J16.L12 J16.R11 J16.R12 J17.DSW2 J18.3 J18.5 J18.7 J18.17 J18.19 J18.45 J18.47 J18.49 J18.51 J18.53 J18.54 J18.55 J18.56 J19.1 J19.5 J20.7 J22.40 J22.41 J23.9 J23.10 M1. SP1.1 SP2.1 T10.1 T10.4 T11.1 T11.4 T12.1 T12.4 T12.M1 T12.M2 U1.1 U2.1 U3.1 U6.18 U6.19 U6.20 U6.21 U7.5 U7.6 U8.5 U11.10 U12.5 U13.5 U14.5 U15.5 U16.5 U20.4 U27.A5 U27.A6 U27.C5 U27.C6 U28.D1 U28.D2
copper on no net: | length 26.8
  Top Layer w0.1: 6.2,23.22 6.65,23.67 7.1,23.22 6.2,23.22 ; 91.725,8.675 92.175,9.125 92.625,8.675 91.725,8.675 ; 93.15,52.8 93.6,52.35 94.05,52.8 93.15,52.8 ; 93.15,63.3 93.6,62.85 94.05,63.3 93.15,63.3
  Top Layer w0.188: 87.12,8.72 ccw(c86.42,8.72) 87.12,8.72
  Top Layer w0.254: 6.41,23.3 6.82,23.3 ; 6.55,23.42 6.6,23.47 6.65,23.47 6.82,23.3 ; 6.87,23.3 6.82,23.3 ; 91.935,8.755 92.345,8.755 ; 92.075,8.875 92.125,8.925 92.175,8.925 92.345,8.755 ; 92.395,8.755 92.345,8.755 ; 93.38,52.72 93.43,52.72 ; 93.38,63.22 93.43,63.22 ; 93.7,52.6 93.65,52.55 93.6,52.55 93.43,52.72 ; 93.7,63.1 93.65,63.05 93.6,63.05 93.43,63.22 ; 93.84,52.72 93.43,52.72 ; 93.84,63.22 93.43,63.22
  Bottom Layer w0.1: 25.05,7.45 25.5,7.9 25.5,7 25.05,7.45 ; 94.05,43.3 94.5,42.85 94.95,43.3 94.05,43.3
  Bottom Layer w0.188: 72.31,62.36 ccw(c71.61,62.36) 72.31,62.36
  Bottom Layer w0.254: 25.3,7.55 25.25,7.5 25.25,7.45 25.42,7.28 ; 25.42,7.23 25.42,7.28 ; 25.42,7.69 25.42,7.28 ; 94.28,43.22 94.33,43.22 ; 94.6,43.1 94.55,43.05 94.5,43.05 94.33,43.22 ; 94.74,43.22 94.33,43.22
  other v4: 4.77,15.775 4.77,24.125 94.89,44.345 94.89,52.695 94.89,57.305 94.89,63.155
  other v5: 19.99,67.09 26.79,67.09
  other v6: 63.55,63.41 88.95,63.41

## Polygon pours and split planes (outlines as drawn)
GND_SHIELD on Top Layer "Polygon_1_Net_GND_SHIELD" (solid, remove dead copper, pour order 29): 20.25,64.29 20,64.04 18.07,64.04 17.8,64.311 17.8,71.371 18.479,72.05 92.571,72.05 93.15,71.471 93.15,64.379 92.25,63.479 92.25,61.071 92.35,60.971 92.35,59.429 91.721,58.8 86.829,58.8 86.45,59.179 86.45,65.479 85.529,66.4 66.921,66.4 66.15,65.629 66.15,59.629 65.521,59 58.421,59 58.05,58.629 58.05,56.579 57.621,56.15 54.729,56.15 54.15,56.729 54.15,63.029 53.629,63.55 45.371,63.55 44.9,63.079 44.9,56.679 44.421,56.2 41.779,56.2 41.25,56.729 41.25,69.279 40.579,69.95 29.621,69.95 29.15,69.479 29.113,64.324 28.83,64.04 27.02,64.04 26.75,64.311 26.75,65.4 26.22,65.93 20.82,65.93 20.25,65.36
+5VS on Top Layer "NONET_L-01_P-001" (solid, pour order 52): 19.94,55.05 19.33,54.44 18.58,54.44 18.45,54.31 18.45,54.18 18.34,54.07 17.51,54.07 16.57,55.01 16.57,56.05 16.82,56.3 18.11,56.3 18.47,55.94 19.81,55.94 19.95,55.8
NetJ2_24 on Top Layer "Polygon_2_Net_N$3" (solid, remove dead copper, pour order 0): 60.44,40.9 60.44,41.6 58.029,41.6 57.84,41.411 57.84,40.89 58.03,40.7 60.24,40.7
NetL24_2 on Top Layer "Polygon_1_Net_N$65" (solid, remove dead copper, pour order 6): 11.26,57.6 15.88,57.6 16.34,57.14 16.34,54.95 17.34,53.95 18.34,53.95 18.39,53.9 18.39,53.55 18.34,53.5 11.22,53.5 10.87,53.85 10.87,57.21
NetL25_1 on Top Layer "Polygon_1_Net_N$90" (solid, remove dead copper, pour order 5): 18,48.45 16.871,48.45 15.941,47.52 11.109,47.52 10.87,47.759 10.87,49.63 11.19,49.95 16.171,49.95 16.385,49.735 16.971,49.15 18.021,49.15 18.2,48.971 18.2,48.529 18.121,48.45
NetL24_1 on Top Layer "Polygon_1_Net_N$65" (solid, remove dead copper, pour order 23): 11.14,50.5 16.29,50.5 16.8,51.01 16.8,52.36 16.97,52.53 18.32,52.53 18.4,52.61 18.4,52.89 18.31,52.98 11.22,52.98 10.87,52.63 10.87,50.77
POWERIN on Top Layer "Polygon_1_Net_POWERIN" (solid, remove dead copper, pour order 15): 1.279,39.55 5.521,39.55 5.9,39.929 5.9,52.929 6.521,53.55 9.171,53.55 9.55,53.929 9.55,56.721 9.171,57.1 0.979,57.1 0.05,56.171 0.05,40.779
GND on Top Layer "GND_L01_P028" (solid, pour order 28): 13,29.45 13,28.21 12.83,28.04 11.56,28.04 11.49,27.97 11.49,27.37 11.56,27.3 13.53,27.3 13.9,27.67 13.9,29.11 14.25,29.46
GND on Top Layer "GND_L01_P027" (solid, pour order 27): 7.679,35.3 7.45,35.071 7.45,31.81 7.92,31.34 12.68,31.34 13,31.02 13,29.45 13.15,29.3 14.09,29.3 14.25,29.46 14.25,30.49 14.47,30.71 15.75,30.71 15.89,30.57 16.71,30.57 16.83,30.69 16.83,34.75 16.27,35.31
VIN on Top Layer "VIN_L01_P026" (solid, pour order 26): 15.69,39.75 15.22,40.22 11.93,40.22 11.59,39.88 11.59,36.79 11.9,36.48 15.25,36.48 15.69,36.92
+3V3 on Top Layer "Polygon_1_Net_+3V3" (solid, remove dead copper, pour order 10): 15.9,45.47 11.23,45.47 10.96,45.2 10.96,43.42 11.17,43.21 13.028,43.21 13.39,42.848 13.39,40.87 13.65,40.61 16.58,40.61 16.855,40.885 16.855,44.515
NetC70_2 on Top Layer "Polygon_1_Net_N$36" (solid, remove dead copper, pour order 12): 2.16,35.28 4.981,35.28 5.16,35.101 5.16,30.76 5.02,30.62 1.34,30.62 0.89,31.07 0.89,34.84 1.33,35.28
GNDIN on Top Layer "Polygon_1_Net_GNDIN" (solid, remove dead copper, pour order 9): 10.66,42.92 10.88,42.7 10.88,38.779 10.551,38.45 7.209,38.45 6.83,38.829 6.83,42.59 7.16,42.92
GND_SHIELD on Bottom Layer "Bottom Layer-GND_SHIELD" (solid, remove dead copper, pour order 50): 87.4,58.8 95.06,58.8 95.43,58.43 95.43,55.699 95.629,55.5 96.929,55.5 97.128,55.699 98.966,55.699 99.168,55.901 99.2,60.571 98.15,61.621 97.921,61.85 94.44,61.85 93.15,63.14 93.15,71.471 92.571,72.05 18.479,72.05 17.8,71.371 17.8,64.311 18.07,64.04 20,64.04 20.25,64.29 20.25,65.36 20.82,65.93 26.093,65.93 26.75,65.273 26.75,64.311 27.02,64.04 28.83,64.04 29.113,64.324 29.15,69.479 29.621,69.95 40.579,69.95 40.786,69.743 40.786,56.874 41.759,55.901 44.271,55.901 45.05,56.68 45.05,62.59 45.79,63.33 53.199,63.33 54.15,62.379 54.15,56.729 54.729,56.15 57.88,56.15 58.42,56.69 58.42,58.42 58.85,58.85 65.521,58.85 66.15,59.479 66.15,65.629 66.921,66.4 85.529,66.4 86.45,65.479 86.45,59.75 86.45,59.179 86.829,58.8
GND on Bottom Layer "GND_L06_P041" (solid, pour order 41): 73.07,18.73 72.9,18.56 72.9,17.54 73.09,17.35 74.74,17.35 75.17,17.78 75.93,17.78 76.09,17.94 76.09,18.42 76.23,18.56 76.95,18.56 77.08,18.69 77.08,21.14 76.12,22.1 76.12,23.82 75.86,24.08 75.22,24.08 74.95,23.81 74.95,22.65 74.5,22.2 74.11,22.2 73.97,22.06 73.97,21.568 73.722,21.32 73.28,21.32 73.03,21.32 72.8,21.09 72.21,20.5 70,20.5 69.91,20.41 69.91,19.11 70.05,18.97 72.21,18.97 72.84,19.6 72.84,20.03 73.22,20.41 75.52,20.41 75.71,20.22 75.71,19.23 75.21,18.73
GND on Bottom Layer "GND_L06_P038" (solid, pour order 38): 49.23,47.49 50.09,48.35 50.89,48.35 51.75,47.49 53.8,47.49 54.12,47.81 54.12,50.68 53.61,51.19 47.22,51.19 46.62,50.59 46.62,47.79 46.92,47.49
VIN on Bottom Layer "VIN_L06_P037" (solid, pour order 37): 59.01,38.78 59.17,38.62 59.17,37.08 58.96,36.87 57.11,36.87 56.92,37.06 56.92,37.89 57.11,38.08 57.36,38.08 57.53,38.25 57.53,38.67 57.64,38.78
GND on Bottom Layer "GND_L06_P035" (solid, pour order 35): 27.62,58.36 27.85,58.13 30.32,58.13 30.58,57.87 30.58,57.17 30.92,56.83 31.94,56.83 32.03,56.92 32.03,58.53 33.26,59.76 33.26,60.65 33.06,60.85 32.48,60.85 32.31,60.68 32.31,60.08 32.15,59.92 30.25,59.92 30.02,60.15 30.02,60.76 29.86,60.92 29.34,60.92 28.66,61.61 27.97,61.61 27.62,61.26
VIN on Bottom Layer "VIN_L06_P036" (solid, pour order 36): 7.64,32.36 7.85,32.15 10.64,32.15 10.89,32.4 10.89,35.73 11.59,36.43 12.56,36.43 12.81,36.68 12.81,38.22 13.15,38.56 15.04,38.56 15.21,38.73 15.21,40.01 15.03,40.19 11.93,40.19 11.71,39.97 11.71,39.63 11.64,39.56 10.96,39.56 10.89,39.49 10.89,38.34 10.62,38.07 7.99,38.07 7.64,37.72
GND on Bottom Layer "Polygon_4_Net_GND" (solid, remove dead copper, pour order 3): 95.39,52.97 96.511,51.85 98.971,51.85 99.2,52.079 99.2,54.16 99.06,54.3 97.821,54.3 97.121,55 95.49,55 95.39,54.9
GNDIN on Bottom Layer "Polygon_2_Net_GNDIN" (solid, remove dead copper, pour order 14): 10.58,38.77 10.39,38.58 7.06,38.58 6.87,38.77 6.87,41.16 3.85,44.18 3.85,52.321 4.579,53.05 9.371,53.05 9.8,52.621 9.8,50.379 9.421,50 7.221,50 6.7,49.479 6.7,46.871 7.321,46.25 9.671,46.25 10.58,45.341
NetJ2_24 on Bottom Layer "Polygon_1_Net_N$3" (solid, remove dead copper, pour order 1): 57.55,39.48 57.68,39.35 59.036,39.35 59.1,39.414 59.1,40.479 59.47,40.849 59.47,41.24 59.35,41.36 57.789,41.36 57.55,41.121
NetC70_2 on Bottom Layer "Polygon_1_Net_N$36" (solid, remove dead copper, pour order 24): 4.91,35.46 5.16,35.21 5.16,30.89 4.43,30.16 1.72,30.16 1.51,30.37 1.51,31.11 0.89,31.73 0.89,34.84 1.51,35.46
GND on Int2 (Sign) "Polygon_1_Net_GND" (solid, remove dead copper, pour order 46): -0.064,72.064 100.064,72.064 100.064,-0.064 -0.064,-0.064
GND_SHIELD on Int2 (Sign) "Polygon_1_Net_GND_SHIELD" (solid, remove dead copper, pour order 16): 20.25,64.29 20,64.04 18.07,64.04 17.8,64.311 17.8,71.371 18.479,72.05 92.571,72.05 93.15,71.471 93.15,64.379 92.25,63.479 92.25,61.071 92.35,60.971 92.35,59.429 91.721,58.8 86.829,58.8 86.45,59.179 86.45,65.479 85.529,66.4 66.921,66.4 66.15,65.629 66.15,59.629 65.521,59 58.421,59 58.05,58.629 58.05,56.579 57.621,56.15 54.729,56.15 54.15,56.729 54.15,63.029 53.629,63.55 45.371,63.55 44.9,63.079 44.9,56.679 44.421,56.2 41.779,56.2 41.25,56.729 41.25,69.279 40.579,69.95 29.621,69.95 29.15,69.479 29.113,64.324 28.83,64.04 27.02,64.04 26.75,64.311 26.75,65.273 26.093,65.93 20.82,65.93 20.25,65.36
VIN on Int2 (Sign) "Polygon_1_Net_VIN" (solid, remove dead copper, pour order 21): 13.77,36.05 17.55,39.83 17.55,43.57 19.33,45.35 22.26,45.35 23.74,46.83 23.74,54.17 22.76,55.15 20.13,55.15 17.55,57.73 17.55,60.11 16.94,60.72 13.92,60.72 9.75,56.55 9.75,46.971 6.45,43.671 6.45,37.72 8.12,36.05
GND on Int3 (Sign) "Polygon_2_Net_GND" (solid, remove dead copper, pour order 30): 0,72.127 100.127,72.127 100.127,0 0,0
GND_SHIELD on Int3 (Sign) "Polygon_1_Net_GND_SHIELD" (solid, remove dead copper, pour order 22): 20.25,64.29 20,64.04 18.07,64.04 17.8,64.311 17.8,71.371 18.479,72.05 92.571,72.05 93.15,71.471 93.15,64.379 92.25,63.479 92.25,61.071 92.35,60.971 92.35,59.429 91.721,58.8 86.829,58.8 86.45,59.179 86.45,65.479 85.529,66.4 66.921,66.4 66.15,65.629 66.15,59.629 65.521,59 58.421,59 58.05,58.629 58.05,56.579 57.621,56.15 54.729,56.15 54.15,56.729 54.15,63.029 53.629,63.55 45.371,63.55 44.9,63.079 44.9,56.679 44.421,56.2 41.779,56.2 41.25,56.729 41.25,69.279 40.579,69.95 29.621,69.95 29.15,69.479 29.113,64.324 28.83,64.04 27.02,64.04 26.75,64.311 26.75,65.273 26.093,65.93 20.82,65.93 20.25,65.36
+3V3 on Int3 (Sign) "Polygon_2_Net_+3V3" (solid, remove dead copper, pour order 47): 14.45,43.829 14.45,44.071 14.829,44.45 16.671,44.45 16.735,44.385 17.1,44.021 17.1,41.079 16.721,40.7 15.529,40.7 14.8,41.429 14.8,43.479
GND on Int4 (GND) "Polygon_6_Net_GND" (solid, remove dead copper, pour order 48): -0.1,-0.1 100.1,-0.1 100.1,72.1 -0.1,72.1
GND_SHIELD on Int4 (GND) "Polygon_1_Net_GND_SHIELD" (solid, remove dead copper, pour order 34): 20.25,64.29 20,64.04 18.07,64.04 17.8,64.311 17.8,71.371 18.479,72.05 92.571,72.05 93.15,71.471 93.15,64.379 92.25,63.479 92.25,61.071 92.35,60.971 92.35,59.429 91.721,58.8 86.829,58.8 86.45,59.179 86.45,65.479 85.529,66.4 66.921,66.4 66.15,65.629 66.15,59.629 65.521,59 58.421,59 58.05,58.629 58.05,56.579 57.621,56.15 54.729,56.15 54.15,56.729 54.15,63.029 53.629,63.55 45.371,63.55 44.9,63.079 44.9,56.679 44.421,56.2 41.779,56.2 41.25,56.729 41.25,69.279 40.579,69.95 29.621,69.95 29.15,69.479 29.113,64.324 28.83,64.04 27.02,64.04 26.75,64.311 26.75,65.273 26.093,65.93 20.82,65.93 20.25,65.36
GND on Int1 (GND) "Polygon_5_Net_GND" (solid, remove dead copper, pour order 45): -0.1,72.1 100.1,72.1 100.1,-0.1 -0.1,-0.1
GND_SHIELD on Int1 (GND) "Polygon_1_Net_GND_SHIELD" (solid, remove dead copper, pour order 31): 20.25,64.29 20,64.04 18.07,64.04 17.8,64.311 17.8,71.371 18.479,72.05 92.571,72.05 93.15,71.471 93.15,64.379 92.25,63.479 92.25,61.071 92.35,60.971 92.35,59.429 91.721,58.8 86.829,58.8 86.45,59.179 86.45,65.479 85.529,66.4 66.921,66.4 66.15,65.629 66.15,59.629 65.521,59 58.421,59 58.05,58.629 58.05,56.579 57.621,56.15 54.729,56.15 54.15,56.729 54.15,63.029 53.629,63.55 45.371,63.55 44.9,63.079 44.9,56.679 44.421,56.2 41.779,56.2 41.25,56.729 41.25,69.279 40.579,69.95 29.621,69.95 29.15,69.479 29.113,64.324 28.83,64.04 27.02,64.04 26.75,64.311 26.75,65.273 26.093,65.93 20.82,65.93 20.25,65.36

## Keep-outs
Keep-Out Layer:
  the board outline again, w0

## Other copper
Top Layer:
  text "+5V" at 17.089,66.82 h0.6 r90
  text "+3V3" at 15.709,66.26 h0.6 r90
  text "+3V3_CPU" at 14.286,63.87 h0.6 r90
  text "WWAN" at 3.23,11.541 h0.7
  text "PCoreBBDSI" at 79.05,10 h0.85
  text "WLAN" at 3.23,9.751 h0.7
  text "c 2021" at 86.097,8.431 h0.85
  text "Rev1.40" at 79.05,8.331 h0.85
  text "WPAN4" at 3.23,8.08 h0.7
  text "RESET" at 9.633,6.78 h1
  text "fs-net.de" at 79.05,6.59 h0.85
Int1 (GND):
  text "Int1" at 92.04,5.648 h1.2
Int2 (Sign):
  text "Int2" at 92.04,5.648 h1.2
Int3 (Sign):
  text "Int3" at 92.04,5.659 h1.2
Int4 (GND):
  text "Int4" at 92.05,5.668 h1.2
Bottom Layer:
  text "PCoreBBDSI" at 79.716,63.64 h0.85
  text "c 2021" at 71.929,62.07 h0.85
  text "Rev1.40" at 79.716,61.97 h0.85
  text "fs-net.de" at 79.716,60.23 h0.85
  text "+" at 6.05,54.05 h1.2

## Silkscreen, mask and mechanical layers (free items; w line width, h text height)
Top Solder:
  circle w0.188: c86.42,8.72 r0.7
  lines w0.1: 6.2,23.22 7.1,23.22 6.65,23.67 6.2,23.22 ; 91.725,8.675 92.175,9.125 92.625,8.675 91.725,8.675 ; 93.15,52.8 93.6,52.35 94.05,52.8 93.15,52.8 ; 93.15,63.3 93.6,62.85 94.05,63.3 93.15,63.3
  lines w0.254: 6.41,23.3 6.82,23.3 ; 6.55,23.42 6.6,23.47 6.65,23.47 6.82,23.3 ; 6.87,23.3 6.82,23.3 ; 91.935,8.755 92.345,8.755 ; 92.075,8.875 92.125,8.925 92.175,8.925 92.345,8.755 ; 92.395,8.755 92.345,8.755 ; 93.38,52.72 93.43,52.72 ; 93.38,63.22 93.43,63.22 ; 93.7,52.6 93.65,52.55 93.6,52.55 93.43,52.72 ; 93.7,63.1 93.65,63.05 93.6,63.05 93.43,63.22 ; 93.84,52.72 93.43,52.72 ; 93.84,63.22 93.43,63.22
  text "+5V" at 17.089,66.82 h0.6 r90
  text "+3V3" at 15.709,66.26 h0.6 r90
  text "+3V3_CPU" at 14.286,63.87 h0.6 r90
  text "WWAN" at 3.23,11.541 h0.7
  text "PCoreBBDSI" at 79.05,10 h0.85
  text "WLAN" at 3.23,9.751 h0.7
  text "c 2021" at 86.097,8.431 h0.85
  text "Rev1.40" at 79.05,8.331 h0.85
  text "WPAN4" at 3.23,8.08 h0.7
  text "RESET" at 9.633,6.78 h1
  text "fs-net.de" at 79.05,6.59 h0.85
Bottom Solder:
  circle w0.188: c71.61,62.36 r0.7
  lines w0.1: 25.05,7.45 25.5,7 25.5,7.9 25.05,7.45 ; 94.05,43.3 94.5,42.85 94.95,43.3 94.05,43.3
  lines w0.254: 25.3,7.55 25.25,7.5 25.25,7.45 25.42,7.28 ; 25.42,7.23 25.42,7.28 ; 25.42,7.69 25.42,7.28 ; 94.28,43.22 94.33,43.22 ; 94.6,43.1 94.55,43.05 94.5,43.05 94.33,43.22 ; 94.74,43.22 94.33,43.22
  text "PCoreBBDSI" at 79.716,63.64 h0.85
  text "c 2021" at 71.929,62.07 h0.85
  text "Rev1.40" at 79.716,61.97 h0.85
  text "fs-net.de" at 79.716,60.23 h0.85
  text "+" at 6.05,54.05 h1.2
  text "-" at 6.05,50.2 h1.2
Dimension:
  the board outline again, w0
Top Name:
  text "PCBBDSI-F3B-050523" at 21.74,76.154 h8
Bottom Name:
  text "PCBBDSI-F3B-050523" at 78.26,76.154 h8
Outline:
  the board outline again, w0.1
